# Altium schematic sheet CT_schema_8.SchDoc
size 256 x 245 mm
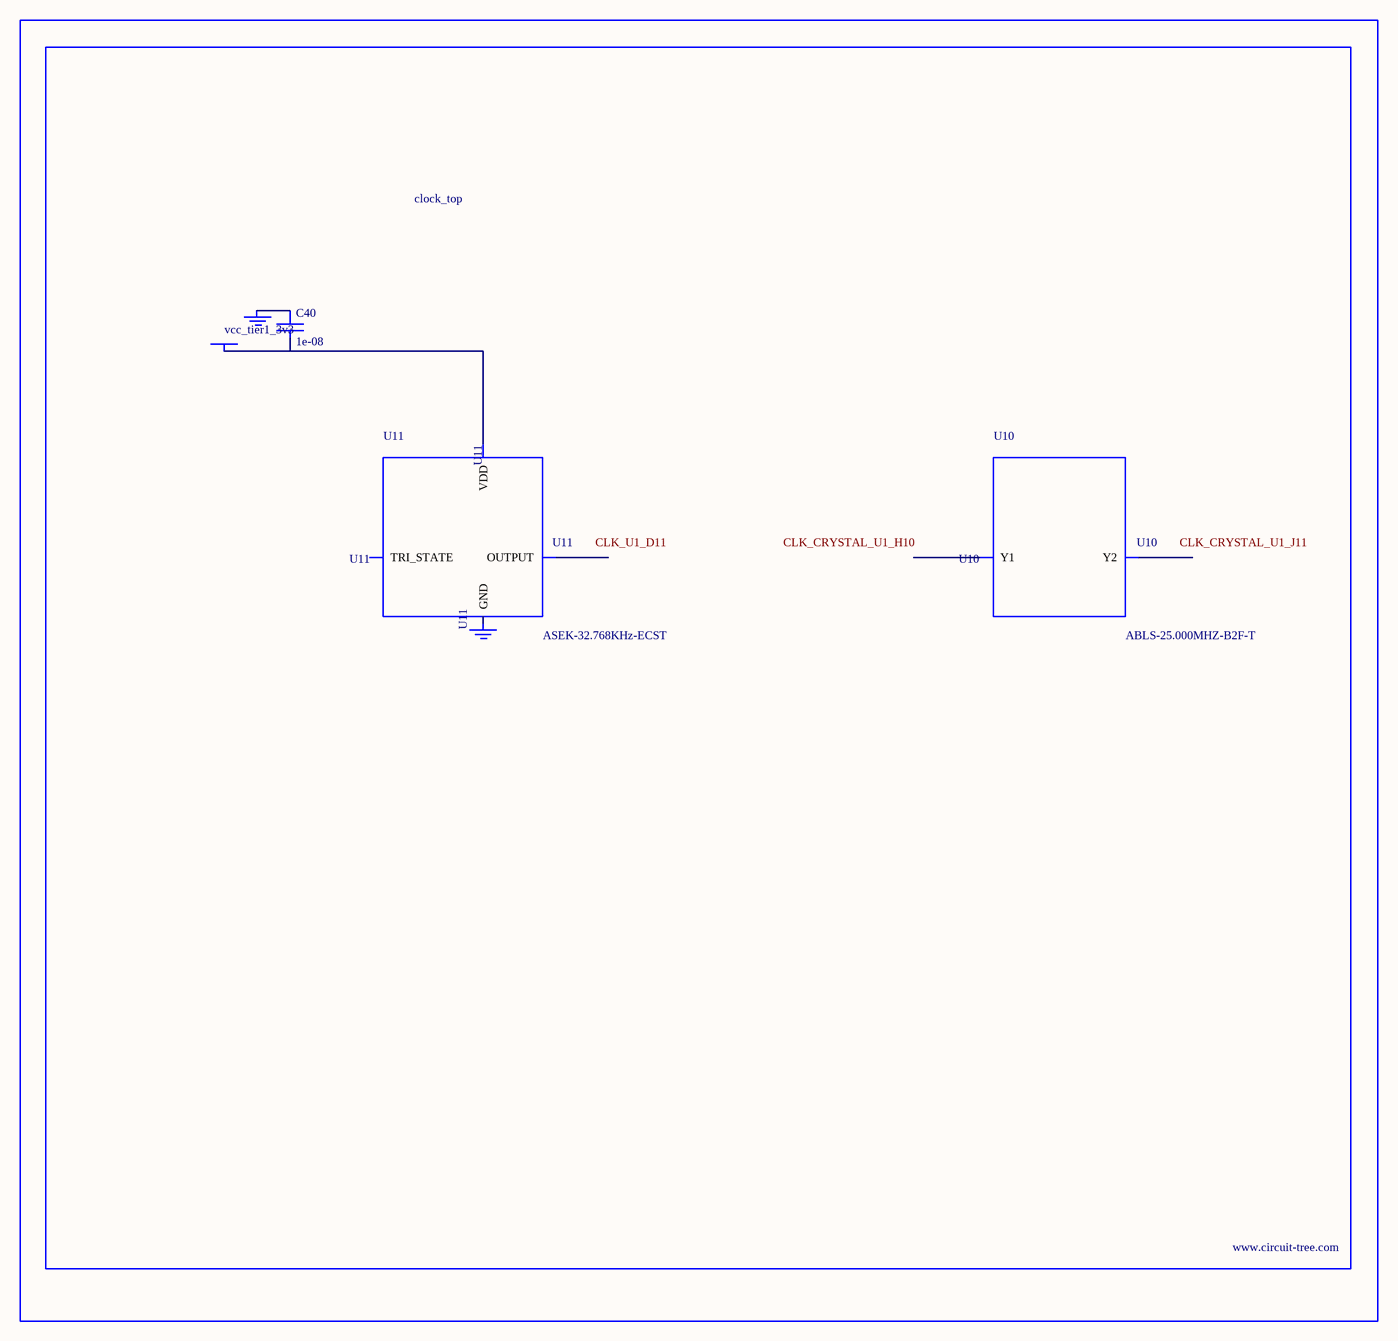
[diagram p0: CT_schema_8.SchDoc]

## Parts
BORDER7  (no value)
C40  1e-08  [C0402]
GND_INSTANCE_7_0  (no value)
GND_INSTANCE_7_1  (no value)
POWER_INSTANCE_7_0  vcc_tier1_3v3
U10  ABLS-25.000MHZ-B2F-T  [ABLS-25.000MHZ-B2F-T]
U11  ASEK-32.768KHz-ECST  [ASEK]

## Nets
NetC40_1: C40.1 GND_INSTANCE_7_0.0(GND)
NetC40_2: C40.2 POWER_INSTANCE_7_0.0(PWR) U11.4(VDD)

Not connected (* = marked no-connect by the designer): GND_INSTANCE_7_1 0(GND); U10 1(Y1) 2(Y2); U11 1(TRI_STATE) 2(GND) 3(OUTPUT)

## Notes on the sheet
- Labels drawn without touching a wire or pin: CLK_CRYSTAL_U1_H10, CLK_CRYSTAL_U1_J11, CLK_U1_D11

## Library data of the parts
BORDER7 = BORDER_PAGE7
C40 = C0402C103K3RAC
GND_INSTANCE_7_0 GND_INSTANCE_7_1 = GND
POWER_INSTANCE_7_0 = PWR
